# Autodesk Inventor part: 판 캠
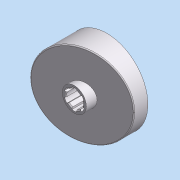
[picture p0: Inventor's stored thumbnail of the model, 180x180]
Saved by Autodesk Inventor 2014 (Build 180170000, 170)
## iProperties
Company: 한국ATC센터
Created: 2012-05
Part Number: 판 캠
Document SubType Name: 모델링
Designer: KYOUNG IL JANG
Mass: 681.587 g
Surface Area: 331.303 cm^2
Volume: 86.8264 cm^3
Density: 7.85 g/cm^3
Material: 강
Appearance: 알루미늄 - 평지
변환 표준: STEP AP214IS
파일 이름: C:\Users\SeoGD\Desktop\?쒗뿕\??stp
전처리기: Build: 253, Release: 2010 SP1 - Date: Wed 07/29/2009
전송 단위: 밀리미터
불확실성: 0.01
Author: KYOUNG IL JANG
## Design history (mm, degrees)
node "작업 평면4"
sketch "스케치1"
  geometry: C1 r 44.5 at (0, 0); 1 further point
  constraints: 1 centre point, 1 coincident
  dimensions: "d25" = 89 diameter of C1
extrude "돌출1" new body sketch "스케치1" distance "d1" = 40; taper "d2" = 0 deg
sketch "스케치2"
  geometry: L1 (-44.5, 15)-(44.5, 38.847); L2 (-44.5, 0)-(-44.5, 40) reference; L3 (-44.5, 40)-(44.5, 40) reference; L4 (44.5, 0)-(44.5, 40) reference; 1 further point
  constraints: 2 end point, 2 point on line
  dimensions: "d26" = 15 distance of L2.start L1.start; "d27" = 75 deg angle of L1 L2
extrude "돌출2" cut sketch "스케치2" stored distance "d5" = 40; taper "d6" = 0 deg
node "작업 평면1"
sketch "스케치3"
  geometry: C1 r 13 at (0, 0); 1 further point
  constraints: 1 centre point, 1 coincident
  dimensions: "d9" = 26 diameter of C1
extrude "돌출3" join sketch "스케치3" distance "d10" = 38; taper "d11" = 0 deg
hole "구멍1" diameter "d14" = 18; stored, may be unused: countersink angle "d18" = 90 deg, drill point angle "d20" = 118 deg; dims "d12" = 10, "d13" = 10, "d15" = 6, "d16" = 4, "d17" = 2, "d19" = 8
feature "쉘2" dims "d29" = 5
sketch "스케치6"
  geometry: C1 r 17.5 at (0, 0); C2 r 14 at (0, 0) reference; 1 further point
  constraints: 1 centre point, 1 coincident
  dimensions: "d28" = 35 diameter of C1
extrude "돌출4" join sketch "스케치6" stored distance "d30" = 38; taper "d31" = 0 deg
fillet "모깎기1" dims "d32" = 3
chamfer "모따기1" distance "d21" = 1; stored, may be unused: second distance "d22" = 2, angle "d23" = 45 deg
sketch "스케치7"
  geometry: L1 (-12.374, 12.374)-(-27.931, 27.931); A1 r 39.5 centre (0, 0) between (-27.931, 27.931) and (0, 39.5) reference; 2 further points
  constraints: 2 end point, 2 point on circle, 1 point on line, 1 vertical alignment, 2 other
  dimensions: "d33" = 45 deg dimension on point (0, 0) L1.start A1.end
feature "리브1" sketch "스케치7" dims "d34" = 5, "d35" = 1, "d36" = 0
fillet "모깎기2" dims "d37" = 3
sketch "스케치8"
  geometry: L1 (2.5, 10.712)-(2.5, 8.646); L2 (-2.5, 10.712)-(-2.5, 8.646); A1 r 11 centre (0, 0) between (2.5, 10.712) and (-2.5, 10.712); A2 r 9 centre (0, 0) between (2.5, 8.646) and (-2.5, 8.646) reference; 1 further point
  constraints: 4 end point, 4 point on circle, 2 parallel, 1 centre point, 1 coincident, 1 vertical
  dimensions: "d41" = 22 diameter of A1; "d42" = 5 distance between parallel lines of L1 L2
extrude "돌출5" cut sketch "스케치8" stored distance "d43" = 38; taper "d44" = 0 deg
fillet "모깎기3" dims "d48" = 1
node "솔리드1"
node "솔리드 본체"
node "곡면 본체"
pattern_circular "원형 패턴1" dims angle "d39" = 360 deg
pattern_circular "원형 패턴2" dims angle "d46" = 360 deg
node "솔리드2"
